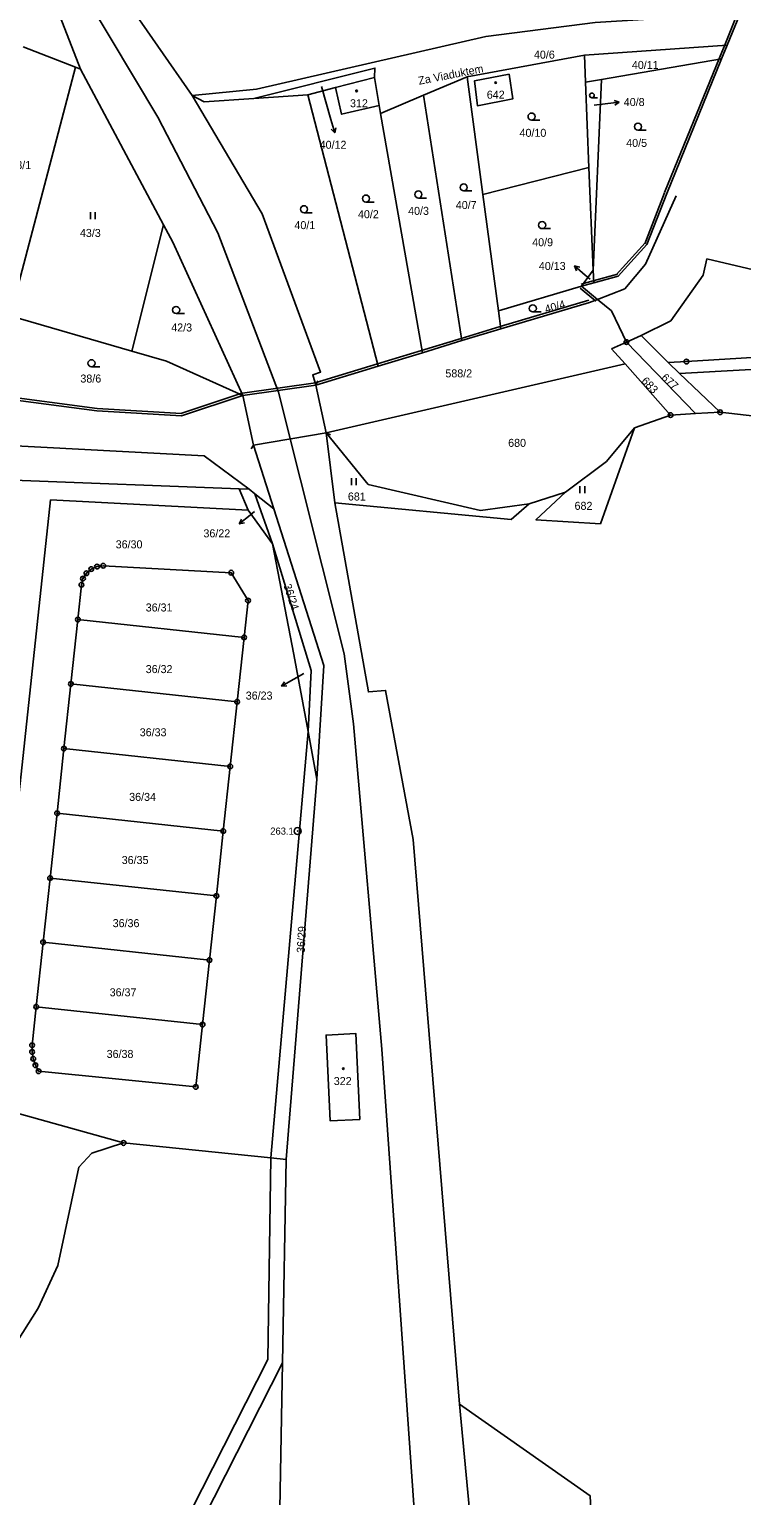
# Model space of a CAD drawing. Extents: x -783948 to -781889, y -1005870 to -1004430.
# Drawn here: x -782413.6 to -782262.2, y -1005661.9 to -1005350.5 of the extents above; entities that cross this region are included whole.
import ezdxf

# ---------------------------------------------------------------- set-up
doc = ezdxf.new("R2010")
doc.units = 0
for name, color, linetype in [('Vrstva 1', 7, 'Continuous'), ('Vrstva 2', 7, 'Continuous'), ('Vrstva 3', 7, 'Continuous'), ('Vrstva 4', 7, 'Continuous'), ('Vrstva 5', 7, 'Continuous'), ('Vrstva 6', 7, 'Continuous'), ('Vrstva 7', 7, 'Continuous'), ('Vrstva 8', 7, 'Continuous')]:
    doc.layers.add(name, color=color, linetype=linetype)

msp = doc.modelspace()

# ---------------------------------------------------------------- linework, layer by layer
at = {"layer": 'Vrstva 1'}
for p, q in [((-782378.99, -1005364.51), (-782402.29, -1005331.02)), ((-782407.07, -1005347.83), (-782402.72, -1005358.91)), ((-782262.57, -1005347.08), (-782265.3, -1005353.79)), ((-782403.77, -1005358.5), (-782414.89, -1005354.18)), ((-782320.58, -1005360.54), (-782295.66, -1005355.95)), ((-782295.66, -1005355.95), (-782265.3, -1005353.79)), ((-782295.42, -1005361.7), (-782295.66, -1005355.95)), ((-782265.3, -1005353.79), (-782266.49, -1005356.71)), ((-782417.72, -1005411.34), (-782403.77, -1005358.5)), ((-782402.72, -1005358.91), (-782403.77, -1005358.5)), ((-782385.13, -1005391.96), (-782402.72, -1005358.91)), ((-782266.49, -1005356.71), (-782292.02, -1005361.11)), ((-782266.49, -1005356.71), (-782278.14, -1005385.34)), ((-782340.27, -1005360.66), (-782348.52, -1005362.81)), ((-782339.25, -1005366.67), (-782340.27, -1005360.66)), ((-782329.83, -1005364.45), (-782320.58, -1005360.54)), ((-782317.24, -1005385.51), (-782320.58, -1005360.54)), ((-782292.02, -1005361.11), (-782295.42, -1005361.7)), ((-782295.42, -1005361.7), (-782294.68, -1005379.82)), ((-782292.02, -1005361.11), (-782293.77, -1005401.6)), ((-782354.39, -1005364.34), (-782365.91, -1005365.14)), ((-782348.52, -1005362.81), (-782354.39, -1005364.34)), ((-782339.49, -1005422.02), (-782354.39, -1005364.34)), ((-782329.83, -1005364.45), (-782338.97, -1005368.32)), ((-782321.68, -1005416.59), (-782329.83, -1005364.45)), ((-782338.97, -1005368.32), (-782339.25, -1005366.67)), ((-782330.09, -1005419.15), (-782338.97, -1005368.32)), ((-782294.68, -1005379.82), (-782317.24, -1005385.51)), ((-782294.68, -1005379.82), (-782293.77, -1005401.6)), ((-782313.93, -1005410.28), (-782317.24, -1005385.51)), ((-782385.13, -1005391.96), (-782391.81, -1005418.85)), ((-782296.24, -1005405.04), (-782293.77, -1005401.6)), ((-782293.77, -1005401.6), (-782293.66, -1005404.33)), ((-782288.5, -1005402.92), (-782293.66, -1005404.33)), ((-782296.24, -1005405.04), (-782313.93, -1005410.28)), ((-782293.66, -1005404.33), (-782296.24, -1005405.04)), ((-782296.24, -1005405.04), (-782292.87, -1005407.82)), ((-782313.42, -1005414.08), (-782294.59, -1005408.48)), ((-782294.59, -1005408.48), (-782292.87, -1005407.82)), ((-782391.81, -1005418.85), (-782417.72, -1005411.34)), ((-782313.93, -1005410.28), (-782313.42, -1005414.08)), ((-782321.68, -1005416.59), (-782313.42, -1005414.08)), ((-782286.72, -1005416.89), (-782283.55, -1005415.47)), ((-782283.55, -1005415.47), (-782277.86, -1005421.26)), ((-782330.09, -1005419.15), (-782321.68, -1005416.59)), ((-782289.89, -1005418.31), (-782286.72, -1005416.89)), ((-782287.02, -1005421.53), (-782289.89, -1005418.31)), ((-782286.72, -1005416.89), (-782272.07, -1005432.09)), ((-782350.55, -1005436.18), (-782287.02, -1005421.53)), ((-782339.49, -1005422.02), (-782330.09, -1005419.15)), ((-782277.34, -1005432.39), (-782287.02, -1005421.53)), ((-782277.86, -1005421.26), (-782275.42, -1005423.59)), ((-782352.7, -1005426.04), (-782339.49, -1005422.02)), ((-782275.42, -1005423.59), (-782266.8, -1005431.8)), ((-782350.55, -1005436.18), (-782352.7, -1005426.04)), ((-782277.34, -1005432.39), (-782284.97, -1005435.14)), ((-782272.07, -1005432.09), (-782277.34, -1005432.39)), ((-782266.8, -1005431.8), (-782272.07, -1005432.09)), ((-782348.71, -1005451.03), (-782350.55, -1005436.18)), ((-782369, -1005448.06), (-782416.99, -1005446.22)), ((-782369, -1005448.06), (-782366.92, -1005448.14)), ((-782367.1, -1005452.62), (-782369, -1005448.06)), ((-782366.92, -1005448.14), (-782365.7, -1005449.1)), ((-782365.7, -1005449.1), (-782361.64, -1005452.3)), ((-782361.96, -1005459.75), (-782365.7, -1005449.1)), ((-782299.64, -1005448.78), (-782307.37, -1005451.28)), ((-782367.1, -1005452.62), (-782361.96, -1005459.75)), ((-782361.96, -1005459.75), (-782357.37, -1005483.27)), ((-782404.77, -1005489.51), (-782403.3, -1005475.84)), ((-782403.3, -1005475.84), (-782367.98, -1005479.63)), ((-782367.98, -1005479.63), (-782369.45, -1005493.31)), ((-782357.37, -1005483.27), (-782354.35, -1005499.64)), ((-782406.25, -1005503.25), (-782404.77, -1005489.51)), ((-782404.77, -1005489.51), (-782369.45, -1005493.31)), ((-782369.45, -1005493.31), (-782370.92, -1005507.04)), ((-782354.35, -1005499.64), (-782362.27, -1005590.2)), ((-782354.35, -1005499.64), (-782352.49, -1005509.72)), ((-782407.72, -1005516.98), (-782406.25, -1005503.25)), ((-782406.25, -1005503.25), (-782370.92, -1005507.04)), ((-782370.92, -1005507.04), (-782372.4, -1005520.77)), ((-782352.49, -1005509.72), (-782359.01, -1005590.51)), ((-782409.21, -1005530.75), (-782407.72, -1005516.98)), ((-782407.72, -1005516.98), (-782372.4, -1005520.77)), ((-782372.4, -1005520.77), (-782373.87, -1005534.54)), ((-782410.68, -1005544.39), (-782409.21, -1005530.75)), ((-782409.21, -1005530.75), (-782373.87, -1005534.54)), ((-782373.87, -1005534.54), (-782375.34, -1005548.19)), ((-782412.15, -1005558.09), (-782410.68, -1005544.39)), ((-782410.68, -1005544.39), (-782375.34, -1005548.19)), ((-782375.34, -1005548.19), (-782376.81, -1005561.88)), ((-782412.15, -1005558.09), (-782376.81, -1005561.88)), ((-782393.59, -1005587.03), (-782422.93, -1005578.83)), ((-782362.27, -1005590.2), (-782393.59, -1005587.03)), ((-782359.01, -1005590.51), (-782362.27, -1005590.2)), ((-782359.01, -1005590.51), (-782359.84, -1005633.71))]:
    msp.add_line(p, q, dxfattribs=at)
for points in [[(-782262.57, -1005347.08), (-782293.38, -1005349), (-782316.62, -1005351.98), (-782365.34, -1005363.17), (-782378.99, -1005364.51)], [(-782365.91, -1005365.14), (-782340.16, -1005358.7), (-782340.27, -1005360.66)], [(-782311.65, -1005359.96), (-782310.88, -1005365.25), (-782318.39, -1005366.69), (-782319.02, -1005361.42), (-782311.65, -1005359.96)], [(-782365.91, -1005365.14), (-782376.48, -1005365.87), (-782378.99, -1005364.51)], [(-782378.99, -1005364.51), (-782364.14, -1005389.62), (-782351.71, -1005423.28), (-782353.39, -1005423.86), (-782352.7, -1005426.04)], [(-782348.52, -1005362.81), (-782347.25, -1005368.51), (-782339.25, -1005366.67)], [(-782278.14, -1005385.34), (-782282.36, -1005396.18), (-782288.5, -1005402.92)], [(-782368.27, -1005428.25), (-782383.15, -1005395.68), (-782385.13, -1005391.96)], [(-782283.55, -1005415.47), (-782277.28, -1005412.35), (-782270.4, -1005402.66), (-782269.63, -1005399.24)], [(-782269.63, -1005399.24), (-782166.16, -1005423.6), (-782144.44, -1005438.47)], [(-782292.87, -1005407.82), (-782289.9, -1005410.26), (-782288.28, -1005413.63), (-782286.72, -1005416.89)], [(-782277.86, -1005421.26), (-782273.98, -1005421.02), (-782230.97, -1005418.4), (-782186.48, -1005430.46), (-782146.48, -1005448.8)], [(-782368.27, -1005428.25), (-782384.45, -1005420.98), (-782391.81, -1005418.85)], [(-782145.62, -1005450.75), (-782187.63, -1005432.5), (-782231.03, -1005421.06), (-782275.42, -1005423.59)], [(-782418.12, -1005429.03), (-782399.25, -1005431.5), (-782381.27, -1005432.53), (-782368.27, -1005428.25)], [(-782368.27, -1005428.25), (-782365.95, -1005438.76), (-782361.64, -1005452.3)], [(-782366.92, -1005448.14), (-782376.44, -1005441.09), (-782428.61, -1005438.3), (-782505.2, -1005433.77)], [(-782162.43, -1005511.23), (-782160.68, -1005470.35), (-782164.17, -1005466.61), (-782187.89, -1005454.31), (-782212.88, -1005444.42), (-782244.09, -1005434.38), (-782266.8, -1005431.8)], [(-782350.55, -1005436.18), (-782341.58, -1005447.12), (-782317.75, -1005452.66), (-782307.37, -1005451.28)], [(-782284.97, -1005435.14), (-782292.24, -1005455.49), (-782305.96, -1005454.63), (-782299.64, -1005448.78)], [(-782299.64, -1005448.78), (-782290.96, -1005442.29), (-782284.97, -1005435.14)], [(-782422.93, -1005578.83), (-782409.11, -1005450.42), (-782367.1, -1005452.62)], [(-782361.64, -1005452.3), (-782351.03, -1005485.58), (-782352.49, -1005509.72)], [(-782322.17, -1005642.53), (-782332.06, -1005522.53), (-782337.9, -1005490.89), (-782341.54, -1005491.2), (-782348.71, -1005451.03)], [(-782307.37, -1005451.28), (-782311.18, -1005454.58), (-782348.71, -1005451.03)], [(-782354.35, -1005499.64), (-782353.72, -1005486.68), (-782361.96, -1005459.75)], [(-782403.3, -1005475.84), (-782402.54, -1005468.45), (-782402.21, -1005467.14), (-782401.49, -1005465.99), (-782400.47, -1005465.11), (-782399.23, -1005464.57), (-782397.89, -1005464.42), (-782370.71, -1005465.88), (-782367.14, -1005471.79), (-782367.98, -1005479.63)], [(-782376.81, -1005561.88), (-782378.23, -1005575.11), (-782411.63, -1005571.8), (-782412.31, -1005570.52), (-782412.78, -1005569.14), (-782413.02, -1005567.7), (-782413.03, -1005566.25), (-782412.15, -1005558.09)], [(-782343.38, -1005582.02), (-782344.22, -1005563.8), (-782350.56, -1005564.09), (-782349.71, -1005582.32), (-782343.38, -1005582.02)], [(-782461.42, -1005652.75), (-782430.52, -1005651.81), (-782411.71, -1005622.13), (-782407.58, -1005613.07), (-782403.07, -1005592.19), (-782400.3, -1005589.18), (-782393.59, -1005587.03)], [(-782459.82, -1005815.99), (-782443.68, -1005792.79), (-782417.66, -1005746.96), (-782388.6, -1005683.51), (-782362.9, -1005633.05), (-782362.27, -1005590.2)], [(-782359.84, -1005633.71), (-782386.44, -1005686.23), (-782414.15, -1005746.16), (-782437.86, -1005788.34), (-782449.27, -1005805.98), (-782458.16, -1005818.32)], [(-782359.84, -1005633.71), (-782360.42, -1005668.62), (-782358.18, -1005701.23), (-782346.04, -1005764.72), (-782338.28, -1005781.93), (-782333.75, -1005785.53), (-782331.2, -1005814.93)], [(-782287.6, -1005803.77), (-782294.69, -1005797.67), (-782307.56, -1005797.88), (-782322.17, -1005642.53)], [(-782322.17, -1005642.53), (-782294.44, -1005661.97), (-782287.6, -1005803.77)]]:
    msp.add_lwpolyline(points, dxfattribs=at)
at = {"layer": 'Vrstva 3'}
for p, q in [((-782294.04, -1005364.99), (-782292.86, -1005364.99)), ((-782306.88, -1005369.74), (-782305.13, -1005369.74)), ((-782284.26, -1005371.88), (-782282.51, -1005371.88)), ((-782342.08, -1005387.16), (-782340.33, -1005387.16)), ((-782330.93, -1005386.29), (-782329.18, -1005386.29)), ((-782321.29, -1005384.78), (-782319.54, -1005384.78)), ((-782400.61, -1005390.8), (-782400.61, -1005389.3)), ((-782399.61, -1005390.8), (-782399.61, -1005389.3)), ((-782355.23, -1005389.42), (-782353.48, -1005389.42)), ((-782304.63, -1005392.8), (-782302.88, -1005392.8)), ((-782382.41, -1005410.82), (-782380.66, -1005410.82)), ((-782306.61, -1005410.49), (-782304.86, -1005410.49)), ((-782400.4, -1005422.14), (-782398.65, -1005422.14)), ((-782345.15, -1005447.31), (-782345.15, -1005445.81)), ((-782344.15, -1005447.31), (-782344.15, -1005445.81)), ((-782296.59, -1005449), (-782296.59, -1005447.5)), ((-782295.59, -1005449), (-782295.59, -1005447.5))]:
    msp.add_line(p, q, dxfattribs=at)
for centre, radius in [((-782294.04, -1005364.49), 0.502), ((-782306.88, -1005368.99), 0.75), ((-782284.26, -1005371.13), 0.75), ((-782321.29, -1005384.03), 0.75), ((-782342.08, -1005386.41), 0.75), ((-782330.93, -1005385.54), 0.75), ((-782355.23, -1005388.67), 0.75), ((-782304.63, -1005392.05), 0.75), ((-782306.61, -1005409.74), 0.75), ((-782382.41, -1005410.07), 0.75), ((-782400.4, -1005421.39), 0.75)]:
    msp.add_circle(centre, radius, dxfattribs=at)
at = {"layer": 'Vrstva 4'}
for p, q in [((-782263.03, -1005346.89), (-782265.76, -1005353.6)), ((-782265.76, -1005353.6), (-782266.95, -1005356.52)), ((-782278.6, -1005385.15), (-782266.95, -1005356.52)), ((-782282.83, -1005396), (-782278.61, -1005385.16)), ((-782282.73, -1005395.84), (-782288.87, -1005402.58)), ((-782293.79, -1005403.85), (-782288.63, -1005402.44)), ((-782296.56, -1005405.43), (-782293.19, -1005408.21)), ((-782296.37, -1005404.56), (-782293.79, -1005403.85)), ((-782313.56, -1005413.6), (-782294.73, -1005408)), ((-782321.82, -1005416.11), (-782313.56, -1005413.6)), ((-782321.83, -1005416.11), (-782330.24, -1005418.67)), ((-782352.85, -1005425.56), (-782339.64, -1005421.54)), ((-782330.24, -1005418.67), (-782339.64, -1005421.54)), ((-782381.43, -1005432.05), (-782368.43, -1005427.77)), ((-782369.22, -1005427.92), (-782368.27, -1005428.25)), ((-782368.34, -1005427.75), (-782352.77, -1005425.54)), ((-782352.7, -1005426.04), (-782368.27, -1005428.25)), ((-782352.31, -1005425.12), (-782352.7, -1005426.04)), ((-782422.18, -1005427.99), (-782399.18, -1005431)), ((-782381.24, -1005432.03), (-782399.22, -1005431)), ((-782365.95, -1005438.76), (-782350.55, -1005436.18)), ((-782349.64, -1005436.6), (-782350.55, -1005436.18)), ((-782366.49, -1005439.6), (-782365.95, -1005438.76))]:
    msp.add_line(p, q, dxfattribs=at)
msp.add_lwpolyline([(-782276.18, -1005385.8), (-782282.68, -1005400.37), (-782287.09, -1005405.6), (-782292.87, -1005407.82)], dxfattribs=at)
at = {"layer": 'Vrstva 5'}
for centre in [(-782314.51, -1005361.78), (-782344.08, -1005363.53), (-782346.89, -1005571.25)]:
    msp.add_circle(centre, 0.175, dxfattribs=at)
at = {"layer": 'Vrstva 6'}
for p, q in [((-782402.26, -1005342.4), (-782386.33, -1005369.12)), ((-782386.33, -1005369.12), (-782373.55, -1005393.66)), ((-782373.55, -1005393.66), (-782360.63, -1005427.55)), ((-782360.63, -1005427.55), (-782346.71, -1005483.1)), ((-782346.71, -1005483.1), (-782344.7, -1005497.96)), ((-782344.7, -1005497.96), (-782338.68, -1005567.1)), ((-782338.68, -1005567.1), (-782330.78, -1005680.08))]:
    msp.add_line(p, q, dxfattribs=at)
at = {"layer": 'Vrstva 7'}
for p, q in [((-782351.54, -1005362.61), (-782349.52, -1005369.59)), ((-782288.27, -1005365.92), (-782289.33, -1005365.55)), ((-782293.59, -1005366.59), (-782291.25, -1005366.29)), ((-782291.25, -1005366.29), (-782288.27, -1005365.92)), ((-782288.27, -1005365.92), (-782289.2, -1005366.54)), ((-782349.52, -1005369.59), (-782348.69, -1005372.47)), ((-782348.69, -1005372.47), (-782349.45, -1005371.65)), ((-782348.69, -1005372.47), (-782348.49, -1005371.37)), ((-782295.46, -1005402.68), (-782297.72, -1005400.71)), ((-782297.72, -1005400.71), (-782296.64, -1005400.99)), ((-782297.72, -1005400.71), (-782297.3, -1005401.75)), ((-782294.44, -1005403.55), (-782295.46, -1005402.68)), ((-782365.73, -1005452.89), (-782366.67, -1005453.64)), ((-782366.67, -1005453.64), (-782369, -1005455.53)), ((-782369, -1005455.53), (-782368.54, -1005454.51)), ((-782369, -1005455.53), (-782367.91, -1005455.29)), ((-782357.41, -1005488.5), (-782360.01, -1005490)), ((-782360.01, -1005490), (-782359.39, -1005489.07)), ((-782360.01, -1005490), (-782358.89, -1005489.93)), ((-782355.27, -1005487.28), (-782357.41, -1005488.5))]:
    msp.add_line(p, q, dxfattribs=at)
at = {"layer": 'Vrstva 8'}
for centre, radius in [((-782286.72, -1005416.89), 0.5), ((-782286.72, -1005416.89), 0.0303), ((-782273.98, -1005421.02), 0.5), ((-782273.98, -1005421.02), 0.0303), ((-782277.34, -1005432.39), 0.5), ((-782277.34, -1005432.39), 0.0303), ((-782266.8, -1005431.8), 0.5), ((-782266.8, -1005431.8), 0.0303), ((-782400.47, -1005465.11), 0.5), ((-782400.47, -1005465.11), 0.0303), ((-782399.23, -1005464.57), 0.5), ((-782399.23, -1005464.57), 0.0303), ((-782397.89, -1005464.42), 0.5), ((-782397.89, -1005464.42), 0.0303), ((-782402.54, -1005468.45), 0.5), ((-782402.21, -1005467.14), 0.5), ((-782402.54, -1005468.45), 0.0303), ((-782402.21, -1005467.14), 0.0303), ((-782401.49, -1005465.99), 0.5), ((-782401.49, -1005465.99), 0.0303), ((-782370.71, -1005465.88), 0.5), ((-782370.71, -1005465.88), 0.0303), ((-782367.14, -1005471.79), 0.5), ((-782367.14, -1005471.79), 0.0303), ((-782403.3, -1005475.84), 0.5), ((-782403.3, -1005475.84), 0.0303), ((-782367.98, -1005479.63), 0.5), ((-782367.98, -1005479.63), 0.0303), ((-782404.77, -1005489.51), 0.5), ((-782404.77, -1005489.51), 0.0303), ((-782369.45, -1005493.31), 0.5), ((-782369.45, -1005493.31), 0.0303), ((-782406.25, -1005503.25), 0.5), ((-782406.25, -1005503.25), 0.0303), ((-782370.92, -1005507.04), 0.5), ((-782370.92, -1005507.04), 0.0303), ((-782407.72, -1005516.98), 0.5), ((-782407.72, -1005516.98), 0.0303), ((-782372.4, -1005520.77), 0.5), ((-782372.4, -1005520.77), 0.0303), ((-782356.6, -1005520.77), 0.75), ((-782356.6, -1005520.77), 0.03), ((-782409.21, -1005530.75), 0.5), ((-782409.21, -1005530.75), 0.0303), ((-782373.87, -1005534.54), 0.5), ((-782373.87, -1005534.54), 0.0303), ((-782410.68, -1005544.39), 0.5), ((-782410.68, -1005544.39), 0.0303), ((-782375.34, -1005548.19), 0.5), ((-782375.34, -1005548.19), 0.0303), ((-782412.15, -1005558.09), 0.5), ((-782412.15, -1005558.09), 0.0303), ((-782376.81, -1005561.88), 0.5), ((-782376.81, -1005561.88), 0.0303), ((-782413.03, -1005566.25), 0.5), ((-782413.02, -1005567.7), 0.5), ((-782413.03, -1005566.25), 0.0303), ((-782413.02, -1005567.7), 0.0303), ((-782412.78, -1005569.14), 0.5), ((-782412.78, -1005569.14), 0.0303), ((-782412.31, -1005570.52), 0.5), ((-782412.31, -1005570.52), 0.0303), ((-782411.63, -1005571.8), 0.5), ((-782411.63, -1005571.8), 0.0303), ((-782378.23, -1005575.11), 0.5), ((-782378.23, -1005575.11), 0.0303), ((-782393.59, -1005587.03), 0.5), ((-782393.59, -1005587.03), 0.0303)]:
    msp.add_circle(centre, radius, dxfattribs=at)

# ---------------------------------------------------------------- texts
at = {"layer": 'Vrstva 2'}
for s, p in [('40/6', (-782306.37, -1005356.68)), ('40/11', (-782285.56, -1005358.87)), ('312', (-782345.46, -1005367.01)), ('642', (-782316.39, -1005365.19)), ('40/8', (-782287.28, -1005366.75)), ('40/10', (-782309.43, -1005373.29)), ('40/12', (-782351.91, -1005375.83)), ('40/5', (-782286.76, -1005375.43)), ('43/1', (-782417.65, -1005380.14)), ('40/7', (-782322.98, -1005388.63)), ('40/2', (-782343.77, -1005390.58)), ('40/3', (-782333.11, -1005389.87)), ('43/3', (-782402.86, -1005394.56)), ('40/1', (-782357.27, -1005392.9)), ('40/9', (-782306.74, -1005396.53)), ('40/13', (-782305.33, -1005401.57)), ('42/3', (-782383.45, -1005414.64)), ('38/6', (-782402.76, -1005425.49)), ('588/2', (-782325.19, -1005424.39)), ('680', (-782311.85, -1005439.15)), ('681', (-782345.91, -1005450.55)), ('682', (-782297.74, -1005452.53)), ('36/30', (-782395.26, -1005460.71)), ('36/22', (-782376.61, -1005458.37)), ('36/31', (-782388.88, -1005474.12)), ('36/32', (-782388.88, -1005487.21)), ('36/23', (-782367.62, -1005492.83)), ('36/33', (-782390.15, -1005500.63)), ('36/34', (-782392.39, -1005514.36)), ('36/35', (-782393.98, -1005527.77)), ('36/36', (-782395.9, -1005541.18)), ('36/37', (-782396.54, -1005555.87)), ('36/38', (-782397.18, -1005568.96)), ('322', (-782348.91, -1005574.72))]:
    msp.add_text(s, height=1.7, dxfattribs=at).set_placement(p)
for s, rotation, p in [('40/4', 16, (-782303.8, -1005410.78)), ('683', 314, (-782283.66, -1005425.27)), ('677', 318, (-782279.45, -1005424.65)), ('36/24', 288, (-782359.63, -1005468.55)), ('36/29', 87, (-782355.1, -1005546.7))]:
    msp.add_text(s, height=1.7, rotation=rotation, dxfattribs=at).set_placement(p)
at = {"layer": 'Vrstva 7'}
msp.add_text('Za Viaduktem', height=1.7, rotation=11, dxfattribs=at).set_placement((-782330.77, -1005362.24))
at = {"layer": 'Vrstva 8'}
msp.add_text('263.1', height=1.5, dxfattribs=at).set_placement((-782362.42, -1005521.52))

doc.saveas('drawing.dxf')
